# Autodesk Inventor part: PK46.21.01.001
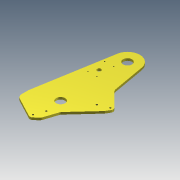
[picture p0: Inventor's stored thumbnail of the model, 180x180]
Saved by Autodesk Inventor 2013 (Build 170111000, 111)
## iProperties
Shininess: 64.0
Length Units: 11269
Angle Units: 11279
Time Units: 11290
Mass Units: 11283
Length Display Precision: 3
Angle Display Precision: 2
Compacted: True
Part Number: PK46.21.01.001
Document SubType Name: Modeling
Created: 2004-12
Designer: Salex
Manufacturer: Standard
Standards Organization: Custom
Material: Steel, Mild
Density: 7.86 g/cm^3
Density: 0.0
Volumn: 0.0
Area: 0.0
PropertySet Name: Model Information
Control State: 0
Master: False
Checked Out: False
Checked Out Date: 2008-10-15
Last Check In Date: 2008-10-15
Author: Salex
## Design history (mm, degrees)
sketch "Sketch1"
  geometry: L1 (-383.695, 252.148)-(-211.988, 855.987) reference; L2 (2.11, 845.209)-(57.62, 533.879); L3 (-106.182, 825.9)-(-105.034, 225.901); L4 (-56.182, 210.9)-(-513.806, 210.9) reference; L5 (-513.806, 170.9)-(-56.182, 170.9) reference; L6 (-330.034, 64.491)-(-130.034, 10.901); L7 (-130.034, 10.901)-(4.59, 160.901); L8 (-6.565, 872.552)-(243.818, 337.9) reference; L9 (53.882, 554.846)-(144.708, 360.901); L10 (144.708, 360.901)-(145.091, 160.901); L11 (145.091, 160.901)-(4.59, 160.901); L12 (-330.034, 64.491)-(-330.034, 170.9); L13 (-330.034, 164.491)-(-214.631, 844.31); C1 r 57.5 at (-106.182, 825.9) reference; C2 r 40 at (-106.182, 825.9) reference; C3 r 125 at (-105.034, 225.901); C4 r 40 at (-105.034, 225.901); A1 r 110 centre (-106.182, 825.9) between (-6.565, 872.552) and (-211.988, 855.987) reference; A2 r 110 centre (-106.182, 825.9) between (-6.565, 872.552) and (2.11, 845.209); 1 further point
  constraints: 18 end point, 4 point on line, 3 centre point, 3 coincident, 3 point on circle, 3 tangent, 1 equal radius, 1 horizontal, 1 parallel, 1 perpendicular
  dimensions: "d10" = 15 deg angle of L6 L5; "d11" = 10 deg angle of L2 L3; "d12" = 80 distance between parallel lines of L8 L9; "d13" = 250 distance between parallel lines of L10 L3; "d14" = 250 diameter of C3; "d15" = 200 distance of L9.end L10.end; "d17" = 600 distance of L3.start C3.centre; "d18" = 25 horizontal distance of L6.end C4.centre; "d19" = 200 distance from line of L6.end L12; "d20" = 65 distance from line of C4.centre L11; "d21" = 150 distance from line of L6.end L11; "d22" = 100 distance of L13.start L6.start
extrude "Extrusion1" new body sketch "Sketch1" distance "d6" = 20; taper "d7" = 0 deg
fillet "Fillet1" dims "d16" = 50
sketch "Эскиз2"
  geometry: L1 (-159.683, 18.846)-(-292.975, 54.561) reference; L2 (-10.311, 144.298)-(-109.531, 33.745) reference; L3 (94.995, 160.901)-(26.9, 160.901) reference; L4 (144.729, 349.823)-(144.995, 210.997) reference; L5 (56.671, 548.891)-(140.01, 370.933) reference; L6 (2.11, 845.209)-(52.728, 561.319) reference; L7 (-330.034, 164.491)-(-214.631, 844.31) reference; L8 (-330.034, 102.857)-(-330.034, 164.491) reference; L9 (-132.394, -13.523)-(-138.697, 26.1) reference; L10 (-77.322, 3.464)-(-107.844, -22.578) reference; L11 (-70.932, 77.506)-(-64.628, 37.883) reference; L12 (-126.003, 60.519)-(-95.481, 86.56) reference; L13 (-303.375, 58.64)-(-129.251, -33.276); L14 (-101.353, -30.185)-(-70.832, -4.143); L15 (-56.537, 17.162)-(-20.601, 126.511); C1 r 7 at (-117.58, -11.167) reference; C2 r 7 at (-85.745, 75.15) reference; A1 r 50 centre (-280.034, 102.857) between (-330.034, 102.857) and (-292.975, 54.561) reference; A2 r 50 centre (-146.742, 67.142) between (-159.683, 18.846) and (-109.531, 33.745) reference; A3 r 50 centre (26.9, 110.901) between (26.9, 160.901) and (-10.311, 144.298) reference; A4 r 50 centre (94.995, 210.901) between (94.995, 160.901) and (144.995, 210.997) reference; A5 r 50 centre (94.73, 349.727) between (144.729, 349.823) and (140.01, 370.933) reference; A6 r 50 centre (101.951, 570.096) between (52.728, 561.319) and (56.671, 548.891) reference; A7 r 110 centre (-106.182, 825.9) between (2.11, 845.209) and (-214.631, 844.31) reference; A8 r 15 centre (-117.58, -11.167) between (-132.394, -13.523) and (-107.844, -22.578) reference; A9 r 15 centre (-85.745, 75.15) between (-70.932, 77.506) and (-95.481, 86.56) reference; A10 r 37.5 centre (-101.663, 31.991) between (-126.003, 60.519) and (-138.697, 26.1) reference; A11 r 37.5 centre (-101.663, 31.991) between (-77.322, 3.464) and (-64.628, 37.883) reference; A12 r 25 centre (-117.58, -11.167) between (-129.251, -33.276) and (-101.353, -30.185); A13 r 47.5 centre (-101.663, 31.991) between (-70.832, -4.143) and (-56.537, 17.162); A14 r 50 centre (26.9, 110.901) between (26.9, 160.901) and (-20.601, 126.511)
  constraints: 15 end point, 15 point on circle, 9 centre point, 6 tangent, 3 concentric, 1 coincident, 1 parallel, 24 other
  dimensions: "d23" = 10 distance between parallel lines of L14 L10
extrude "Выдавливание2" join sketch "Эскиз2" distance "d24" = 20; taper "d25" = 0 deg
sketch "Эскиз3"
  geometry: L1 (94.995, 160.901)-(26.9, 160.901) reference; L2 (144.729, 349.823)-(144.995, 210.997) reference; L3 (-9.857, 144.797)-(167.611, 337.239); L4 (144.801, 312.505)-(144.995, 210.997); L5 (94.995, 160.901)-(26.9, 160.901); C1 r 26 at (132.692, 369.441) reference; A1 r 50 centre (26.9, 110.901) between (26.9, 160.901) and (-20.601, 126.511) reference; A2 r 50 centre (94.995, 210.901) between (94.995, 160.901) and (144.995, 210.997) reference; A3 r 37.5 centre (132.692, 369.441) between (132.764, 331.941) and (164.726, 349.945) reference; A4 r 50 centre (94.995, 210.901) between (94.995, 160.901) and (144.995, 210.997); A5 r 50 centre (26.9, 110.901) between (26.9, 160.901) and (-9.857, 144.797); 1 further point
  constraints: 7 point on circle, 6 end point, 4 centre point, 2 concentric, 2 point on line, 2 tangent, 1 coincident, 1 collinear, 10 other
  dimensions: "d26" = 10 dimension on A3
extrude "Выдавливание3" cut sketch "Эскиз3" stored distance "d27" = 20; taper "d28" = 0 deg
sketch "Эскиз4"
  geometry: L1 (-9.857, 144.797)-(144.801, 312.505) reference; L2 (144.729, 349.823)-(144.801, 312.505) reference; L3 (56.671, 548.891)-(140.01, 370.933) reference; L4 (2.11, 845.209)-(52.728, 561.319) reference; L5 (-330.034, 164.491)-(-214.631, 844.31) reference; L6 (-330.034, 102.857)-(-330.034, 164.491) reference; L7 (-303.375, 58.64)-(-129.251, -33.276) reference; L8 (-101.353, -30.185)-(-70.832, -4.143) reference; L9 (-56.537, 17.162)-(-20.601, 126.511) reference; L10 (66.427, 534.91)-(190.533, 409.61); L11 (144.801, 312.505)-(167.611, 337.239); L12 (194.127, 379.021)-(173.269, 344.747); A1 r 50 centre (94.73, 349.727) between (144.729, 349.823) and (140.01, 370.933) reference; A2 r 50 centre (101.951, 570.096) between (52.728, 561.319) and (56.671, 548.891) reference; A3 r 110 centre (-106.182, 825.9) between (2.11, 845.209) and (-214.631, 844.31) reference; A4 r 50 centre (-280.034, 102.857) between (-330.034, 102.857) and (-303.375, 58.64) reference; A5 r 25 centre (-117.58, -11.167) between (-129.251, -33.276) and (-101.353, -30.185) reference; A6 r 47.5 centre (-101.663, 31.991) between (-70.832, -4.143) and (-56.537, 17.162) reference; A7 r 50 centre (26.9, 110.901) between (-9.857, 144.797) and (-20.601, 126.511) reference; A8 r 47.5 centre (132.692, 369.441) between (167.611, 337.239) and (173.269, 344.747); A9 r 50 centre (101.951, 570.096) between (52.728, 561.319) and (66.427, 534.91); A10 r 25 centre (172.77, 392.017) between (194.127, 379.021) and (190.533, 409.61)
  constraints: 7 end point, 6 point on circle, 6 tangent, 3 centre point, 1 coincident, 1 concentric
extrude "Выдавливание4" join sketch "Эскиз4" distance "d30" = 20; taper "d31" = 0 deg
sketch "Эскиз6"
  geometry: C1 r 17.5 at (-170.819, 635.776) reference
  constraints: 1 centre point, 2 other
extrude "Выдавливание6" cut sketch "Эскиз6" stored distance "d36" = 10; taper "d37" = 0 deg
sketch "Sketch7"
  geometry: C1 r 5.5 at (-210.991, 725.699) reference; C2 r 5.5 at (-130.704, 575.853) reference; C3 r 5.5 at (-210.704, 575.699) reference; C4 r 5.5 at (-130.991, 725.852) reference; 1 further point
  constraints: 4 centre point, 8 other
  dimensions: "d39" = 11 diameter of C3 (derived)
hole "Hole1" sketch "Sketch7" at (-210.991, 725.699), (-130.991, 725.852), (-130.704, 575.853), (-210.704, 575.699) diameter "d40" = 9.376; stored, may be unused: countersink angle "d44" = 90 deg, drill point angle "d46" = 118 deg; dims "d41" = 12, "d42" = 4, "d43" = 2, "d45" = 8
sketch "Sketch8"
  geometry: C1 r 9 at (172.77, 392.017) reference; C2 r 9 at (87.755, 356.854) reference; C3 r 9 at (-88.174, 80.145) reference; C4 r 9 at (-120.009, -6.172) reference; 1 further point
  constraints: 4 centre point, 8 other
  dimensions: "d47" = 18 diameter of C1 (derived)
hole "Hole2" sketch "Sketch8" at (172.77, 392.017), (87.755, 356.854), (-88.174, 80.145), (-120.009, -6.172) diameter "d48" = 15.294; stored, may be unused: countersink angle "d52" = 90 deg, drill point angle "d54" = 118 deg; dims "d49" = 15, "d50" = 4, "d51" = 2, "d53" = 8
body "Solid1"
node "Reference1"
node "Reference2"
node "Reference5"
node "Reference6"
node "Reference7"
node "Reference8"
